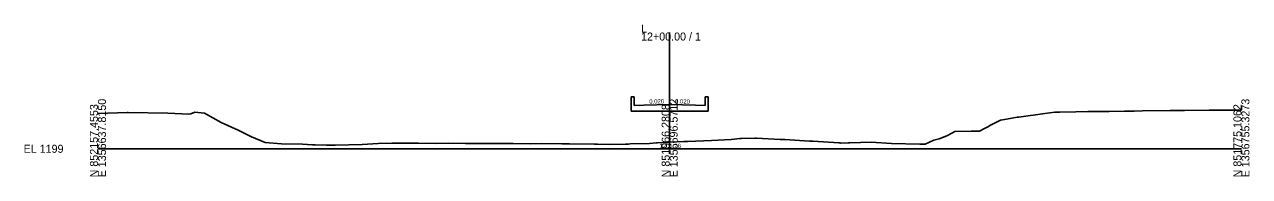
# Model space of a CAD drawing. Extents: x -26 to 4603, y -10 to 4066.
# Drawn here: x -25.7 to 402.8, y 1490.3 to 1543.4 of the extents above; entities that cross this region are included whole.
import ezdxf

# ---------------------------------------------------------------- set-up
doc = ezdxf.new("R2010")
doc.units = 0
for name, color, linetype in [('Exist Cross Section Cell', 7, 'Continuous'), ('Exist XS Center Line Elevation Label', 7, 'Continuous'), ('Exist XS Ground Line', 7, 'Continuous'), ('Prop XS Bridge', 7, 'Continuous'), ('Prop XS Dump Level', 7, 'Continuous'), ('Prop XS SE Text', 7, 'Continuous')]:
    doc.layers.add(name, color=color, linetype=linetype)

msp = doc.modelspace()

# ---------------------------------------------------------------- linework, layer by layer
at = {"layer": 'Exist Cross Section Cell'}
for p, q in [((200, 1500), (200, 1540.64)), ((0, 1500), (200, 1500)), ((200, 1500), (400, 1500))]:
    msp.add_line(p, q, dxfattribs=at)
at = {"layer": 'Exist XS Ground Line'}
for p, q in [((32.45, 1512.26), (33.87, 1512.79)), ((33.87, 1512.79), (37.23, 1512.39)), ((331.3, 1512.28), (334.74, 1512.79)), ((334.74, 1512.79), (335.27, 1512.78)), ((335.27, 1512.78), (336.49, 1512.81)), ((336.49, 1512.81), (342.12, 1512.94)), ((342.12, 1512.94), (346.32, 1513.03)), ((346.32, 1513.03), (346.85, 1513.04)), ((346.85, 1513.04), (351.31, 1513.03)), ((351.31, 1513.03), (353.74, 1513.02)), ((353.74, 1513.02), (359.13, 1513.14)), ((359.13, 1513.14), (362.48, 1513.19)), ((362.48, 1513.19), (365.39, 1513.25)), ((365.39, 1513.25), (375.03, 1513.41)), ((375.03, 1513.41), (380.1, 1513.43)), ((380.1, 1513.43), (388.72, 1513.47)), ((388.72, 1513.47), (392.65, 1513.49)), ((392.65, 1513.49), (400, 1513.55)), ((0, 1512.3), (10.22, 1512.67)), ((10.22, 1512.67), (10.58, 1512.66)), ((10.58, 1512.66), (24.46, 1512.49)), ((24.46, 1512.49), (31.84, 1512.06)), ((31.84, 1512.06), (32.45, 1512.26)), ((37.23, 1512.39), (43.14, 1509.21)), ((43.14, 1509.21), (49.11, 1506.46)), ((312.26, 1508.25), (315.7, 1509.97)), ((315.7, 1509.97), (317.86, 1510.36)), ((317.86, 1510.36), (321.51, 1511.03)), ((321.51, 1511.03), (322.13, 1511.1)), ((322.13, 1511.1), (331.3, 1512.28)), ((49.11, 1506.46), (53.69, 1504.17)), ((53.69, 1504.17), (58.53, 1502.14)), ((295.84, 1504.05), (297.2, 1504.66)), ((297.2, 1504.66), (299.78, 1506.04)), ((299.78, 1506.04), (305.51, 1506.2)), ((305.51, 1506.2), (308.36, 1506.15)), ((308.36, 1506.15), (310.11, 1507.09)), ((310.11, 1507.09), (311.3, 1507.7)), ((311.3, 1507.7), (312.26, 1508.25)), ((58.53, 1502.14), (64.17, 1501.75)), ((64.17, 1501.75), (71.55, 1501.55)), ((71.55, 1501.55), (75.07, 1501.39)), ((75.07, 1501.39), (76, 1501.32)), ((76, 1501.32), (79.94, 1501.21)), ((79.94, 1501.21), (82.1, 1501.25)), ((82.1, 1501.25), (82.98, 1501.29)), ((82.98, 1501.29), (92.45, 1501.53)), ((92.45, 1501.53), (97.97, 1501.83)), ((97.97, 1501.83), (102.77, 1501.99)), ((102.77, 1501.99), (105.29, 1502.01)), ((105.29, 1502.01), (108.55, 1501.96)), ((108.55, 1501.96), (112.09, 1501.98)), ((112.09, 1501.98), (118.54, 1501.89)), ((118.54, 1501.89), (122.63, 1501.92)), ((122.63, 1501.92), (128.53, 1501.85)), ((128.53, 1501.85), (133.09, 1501.88)), ((133.09, 1501.88), (138.52, 1501.82)), ((138.52, 1501.82), (141.98, 1501.79)), ((141.98, 1501.79), (145.23, 1501.83)), ((145.23, 1501.83), (151.3, 1501.77)), ((151.3, 1501.77), (155.13, 1501.82)), ((155.13, 1501.82), (162.25, 1501.72)), ((162.25, 1501.72), (164.98, 1501.76)), ((164.98, 1501.76), (173.7, 1501.58)), ((173.7, 1501.58), (174.76, 1501.6)), ((174.76, 1501.6), (178.98, 1501.47)), ((178.98, 1501.47), (184.6, 1501.62)), ((184.6, 1501.62), (185.6, 1501.65)), ((185.6, 1501.65), (186.2, 1501.67)), ((186.2, 1501.67), (192.97, 1501.88)), ((192.97, 1501.88), (195.39, 1502.03)), ((195.39, 1502.03), (195.75, 1502.03)), ((195.75, 1502.03), (200, 1502.26)), ((200, 1502.26), (204.94, 1502.52)), ((204.94, 1502.52), (206.23, 1502.52)), ((206.23, 1502.52), (214.65, 1502.93)), ((214.65, 1502.93), (221.55, 1503.28)), ((221.55, 1503.28), (224.58, 1503.55)), ((224.58, 1503.55), (225.1, 1503.56)), ((225.1, 1503.56), (229.77, 1503.75)), ((229.77, 1503.75), (230.42, 1503.76)), ((230.42, 1503.76), (238.69, 1503.23)), ((238.69, 1503.23), (240.28, 1503.26)), ((240.28, 1503.26), (248.94, 1502.69)), ((248.94, 1502.69), (250.15, 1502.7)), ((250.15, 1502.7), (259.18, 1502.08)), ((259.18, 1502.08), (259.55, 1502.05)), ((259.55, 1502.05), (259.85, 1502.01)), ((259.85, 1502.01), (262.6, 1502.13)), ((262.6, 1502.13), (263, 1502.07)), ((263, 1502.07), (270.46, 1502.31)), ((270.46, 1502.31), (277.64, 1501.79)), ((277.64, 1501.79), (287.54, 1501.58)), ((287.54, 1501.58), (289.43, 1501.63)), ((289.43, 1501.63), (292.43, 1502.97)), ((292.43, 1502.97), (294.3, 1503.49)), ((294.3, 1503.49), (295.84, 1504.05))]:
    msp.add_line(p, q, dxfattribs=at)
at = {"layer": 'Prop XS Bridge'}
for p, q in [((186.58, 1518.17), (186.58, 1515.17)), ((187.58, 1518.17), (186.58, 1518.17)), ((187.58, 1515.17), (187.58, 1518.17)), ((212.42, 1515.17), (212.42, 1518.17)), ((212.42, 1518.17), (213.42, 1518.17)), ((213.42, 1518.17), (213.42, 1515.17)), ((186.58, 1515.17), (186.58, 1513.17)), ((213.42, 1513.2), (186.58, 1513.2)), ((191, 1515.24), (187.58, 1515.17)), ((191, 1515.24), (200, 1515.42)), ((200, 1515.42), (209, 1515.24)), ((209, 1515.24), (212.42, 1515.17)), ((213.42, 1515.17), (213.42, 1513.17))]:
    msp.add_line(p, q, dxfattribs=at)
at = {"layer": 'Prop XS Dump Level'}
for p, q in [((191, 1515.24), (200, 1515.42)), ((200, 1515.42), (209, 1515.24))]:
    msp.add_line(p, q, dxfattribs=at)

# ---------------------------------------------------------------- texts
at = {"layer": 'Exist Cross Section Cell'}
for s, p in [('L', (190, 1540.64)), ('12+00.00 / 1', (190, 1537.84)), ('EL 1199', (-26, 1498.6))]:
    msp.add_text(s, height=2.8, dxfattribs=at).set_placement(p)
for s, p in [('E 1356637.8150', (2.8, 1490)), ('E 1356696.5712', (202.8, 1490)), ('E 1356755.3273', (402.8, 1490)), ('N 852157.4553', (0, 1490)), ('N 851966.2808', (200, 1490)), ('N 851775.1062', (400, 1490))]:
    msp.add_text(s, height=2.8, rotation=90, dxfattribs=at).set_placement(p)
at = {"layer": 'Exist XS Center Line Elevation Label'}
msp.add_text('1201.26', height=1.5, dxfattribs=at).set_placement((196.46, 1500.27))
at = {"layer": 'Prop XS SE Text'}
for rotation, p in [(1.1458, (192.88, 1515.78)), (358.8542, (201.88, 1515.89))]:
    msp.add_text('0.020', height=1.5, rotation=rotation, dxfattribs=at).set_placement(p)

doc.saveas('drawing.dxf')
